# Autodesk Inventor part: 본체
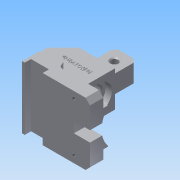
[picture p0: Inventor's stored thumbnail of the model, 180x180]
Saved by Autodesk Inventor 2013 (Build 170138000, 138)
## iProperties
Created: 2016-11
Part Number: 본체
Material: 알루미늄 6061
Document SubType Name: Modeling
Designer: user
Density: 2.71 g/cm^3
Mass: 462.813 g
Surface Area: 317.449 cm^2
Volume: 170.78 cm^3
Author: user
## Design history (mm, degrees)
sketch "스케치1"
  geometry: L1 (13, 0)-(63, 0); L2 (63, 0)-(63, -15); L3 (-13, -15)-(-13, 0); L4 (-10, -15)-(-10, -8); L5 (-10, -8)-(10, -8); L6 (10, -8)-(10, -15); L7 (63, -15)-(10, -15); L8 (-10, -15)-(-13, -15); A1 r 13 centre (0, 0) between (13, 0) and (-13, 0); 1 further point
  constraints: 16 end point, 5 parallel, 2 perpendicular, 2 point on circle, 1 centre point, 1 coincident, 1 collinear, 1 horizontal, 1 horizontal alignment, 1 tangent
  dimensions: "d0" = 26 diameter of A1; "d1" = 7 distance between parallel lines of L5 L8; "d2" = 15 distance between parallel lines of L7 L1; "d3" = 3 distance between parallel lines of L4 L3; "d4" = 20 distance between parallel lines of L6 L4; "d5" = 63 distance from line of L2 point (0, 0)
extrude "돌출1" new body sketch "스케치1" stored distance "d7" = 70; taper "d8" = 0 deg
sketch "스케치2"
  geometry: L1 (-13, -15)-(-13, 0) reference; L2 (-13, -3)-(-27, -3); L3 (-27, -3)-(-27, 27); L4 (-27, 27)-(-9, 45); L5 (-9, 45)-(1, 45); L6 (1, 45)-(1, 75); L7 (1, 75)-(26, 75); L8 (26, 75)-(26, 45); L9 (26, 45)-(31, 45); L10 (31, 45)-(31, 5); L11 (31, 5)-(63, 5); L12 (63, 5)-(63, 0); L13 (63, -15)-(10, -15) reference; L14 (63, 0)-(63, -15) reference; L15 (-10, -15)-(-13, -15) reference; L16 (-13, -3)-(63, -3); 1 further point
  constraints: 24 end point, 6 parallel, 5 perpendicular, 2 collinear, 2 point on line
  dimensions: "d9" = 20 distance between parallel lines of L13 L11; "d10" = 58 distance between parallel lines of L10 L3; "d11" = 90 distance between parallel lines of L14 L3; "d12" = 5 distance between parallel lines of L10 L8; "d13" = 25 distance between parallel lines of L6 L8; "d14" = 18 horizontal distance of L3.end L4.end; "d15" = 45 deg angle of L5 L4; "d16" = 60 distance between parallel lines of L15 L5; "d17" = 90 distance between parallel lines of L15 L7; "d18" = 12 distance between parallel lines of L15 L2
extrude "돌출2" join sketch "스케치2" stored distance "d19" = 40; taper "d20" = 0 deg
sketch "스케치3"
  geometry: L1 (-27, 27)-(31, 27); L2 (-13, -3)-(-27, -3) reference; L3 (-27, -3)-(-27, 27) reference; L4 (-27, 27)-(-27, 37); L5 (-27, 37)-(24, 37); L6 (24, 37)-(24, 41.5); L7 (24, 41.5)-(31, 41.5); L8 (31, 45)-(31, 5) reference; L9 (31, 41.5)-(31, 27); 1 further point
  constraints: 12 end point, 3 point on line, 2 parallel, 1 collinear, 1 horizontal, 1 perpendicular
  dimensions: "d21" = 30 distance between parallel lines of L2 L1; "d22" = 20 diameter of L5 L1; "d23" = 29 diameter of L7 L1; "d24" = 7 distance between parallel lines of L8 L6
revolve "회전1" sketch "스케치3" stored, may be unused: angle "d25" = 90 deg
sketch "스케치4"
  geometry: L1 (0, 30)-(40, 30) reference; L2 (0, 0)-(0, 30) reference; L3 (0, 0)-(40, 0) reference; L4 (40, 30)-(40, 0) reference; L5 (0, 30)-(10, 30); L6 (10, 30)-(10, 0); L7 (10, 0)-(0, 0); L8 (0, 0)-(0, 30); L9 (0, 0)-(40, 0) reference; L10 (40, 30)-(30, 30); L11 (30, 30)-(30, 0); L12 (30, 0)-(40, 0); L13 (40, 0)-(40, 30); 1 further point
  constraints: 16 end point, 4 collinear, 4 parallel, 2 horizontal, 2 perpendicular, 2 point on line
  dimensions: "d26" = 10 distance between parallel lines of L2 L6; "d27" = 10 distance between parallel lines of L4 L11
extrude "돌출3" cut sketch "스케치4" distance "d28" = 40; taper "d29" = 0 deg
sketch "스케치5"
  geometry: L1 (-25, 0)-(-25, 30) reference; L2 (37, -60)-(-16, -60) reference; 2 further points
  dimensions: "d30" = 12.5 distance from line of L1 point (-12.5, 17); "d31" = 77 distance from line of L2 point (-12.5, 17)
hole "구멍1" sketch "스케치5" at (-12.5, 17) diameter "d32" = 8; stored, may be unused: countersink angle "d36" = 90 deg, drill point angle "d38" = 118 deg; dims "d33" = 6, "d34" = 4, "d35" = 2, "d37" = 8
sketch "스케치6"
  geometry: L1 (55, 15)-(70, 15) reference; L2 (15, 20)-(55, 20) reference; L3 (29, 13.627)-(29, 0); L4 (41, 13.627)-(41, 0); L5 (41, 0)-(29, 0); L6 (16.106, 20)-(53.894, 20); L7 (35, 0)-(35, 20); L8 (15, 20)-(55, 20) reference; L9 (70, 0)-(0, 0) reference; C1 r 10 at (35, 42) reference; A1 r 29 centre (35, 42) between (16.106, 20) and (29, 13.627); A2 r 29 centre (35, 42) between (41, 13.627) and (53.894, 20); 1 further point
  constraints: 10 end point, 4 point on circle, 2 centre point, 2 collinear, 2 midpoint, 2 point on line, 1 coincident, 1 parallel, 1 perpendicular, 1 vertical alignment, 1 other
  dimensions: "d40" = 12 distance between parallel lines of L4 L3; "d41" = 29 radius of A1; "d42" = 29 radius of A2
extrude "돌출4" cut sketch "스케치6" distance "d44" = 18; taper "d45" = 0 deg
sketch "스케치7"
  geometry: L1 (50, -15)-(50, 0) reference; 2 further points
  dimensions: "d46" = 27.5 vertical distance of point (-13, -35) point (32, -7.5); "d47" = 18 distance from line of L1 point (32, -7.5)
hole "구멍2" sketch "스케치7" at (32, -7.5) diameter "d48" = 3.459; stored, may be unused: countersink angle "d52" = 90 deg, drill point angle "d54" = 118 deg; dims "d49" = 6, "d50" = 4, "d51" = 2, "d53" = 8
sketch "스케치8"
  geometry: L1 (31, 45)-(-9, 45) reference; L2 (31, 5)-(31, 45) reference; 1 further point
  constraints: 1 other
  dimensions: "d55" = 18 distance from line of L1 point (6, 27); "d56" = 25 distance from line of L2 point (6, 27)
feature "엠보싱1" sketch "스케치8" dims "d57" = 0.5, "d58" = 0
chamfer "모따기1" distance "d59" = 4; stored, may be unused: second distance "d60" = 2, angle "d61" = 45 deg
fillet "모깎기1" dims "d62" = 5
chamfer "모따기2" distance "d63" = 5; stored, may be unused: second distance "d64" = 2, angle "d65" = 45 deg
fillet "모깎기2" dims "d66" = 3
chamfer "모따기3" distance "d67" = 1; stored, may be unused: second distance "d68" = 2, angle "d69" = 45 deg
node "솔리드1"
mirror "대칭1"
other parameters: "d39" = 58
